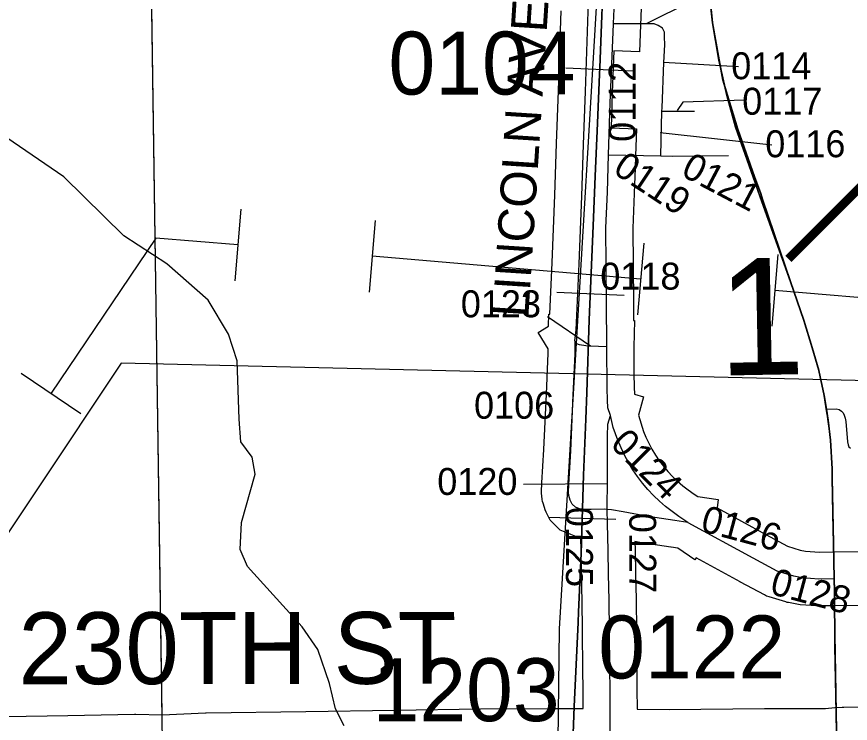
# Model space of a CAD drawing. Extents: x 23.6 to 68.7, y -63 to -29.
# Drawn here: x 43.509 to 44.437, y -46.572 to -45.786 of the extents above; entities that cross this region are included whole.
import ezdxf

# ---------------------------------------------------------------- set-up
doc = ezdxf.new("R2010")
doc.units = 0
for name, color, linetype in [('tdCoHydroRiver', 7, 'Continuous'), ('tdCoInstRd', 7, 'Continuous'), ('tdCoPipe', 7, 'Continuous'), ('tdCoPipe3', 7, 'Continuous'), ('tdCoPriCL', 7, 'Continuous'), ('tdCoPrimary', 7, 'Continuous'), ('tdCoPriNonDiv', 7, 'Continuous'), ('tdCoPriNonDivCL', 7, 'Continuous'), ('tdCoRRCL', 7, 'Continuous'), ('tdCoSecRdNmbr', 7, 'Continuous'), ('tdCoSecRdTxt', 7, 'Continuous'), ('tdCoSecRteBand', 7, 'Continuous'), ('tdCoSecRteCL', 7, 'Continuous'), ('tdCoSectLine', 7, 'Continuous'), ('tdCoSectLinePart', 7, 'Continuous'), ('tdCoSectNmbr', 7, 'Continuous'), ('tdCoSurfConc', 7, 'Continuous'), ('tdCoSurfConcUnbanded', 7, 'Continuous'), ('tdCoSurfGravel', 7, 'Continuous'), ('tdCoSurfGravelUnbanded', 7, 'Continuous'), ('tdStHwyPriRefPost1', 7, 'Continuous')]:
    doc.layers.add(name, color=color, linetype=linetype)

msp = doc.modelspace()

# ---------------------------------------------------------------- linework, layer by layer
at = {"layer": 'tdCoHydroRiver'}
msp.add_lwpolyline([(43.87358, -46.57498), (43.86393, -46.55613), (43.85735, -46.52778), (43.84436, -46.49002), (43.82676, -46.46493), (43.76614, -46.39763), (43.75806, -46.37876), (43.75936, -46.34876), (43.77464, -46.29494), (43.7713, -46.27603), (43.75851, -46.25879), (43.75669, -46.23355), (43.7545, -46.16885), (43.74475, -46.13896), (43.72229, -46.10128), (43.67613, -46.06068), (43.62848, -46.02956), (43.56155, -45.9639), (43.4837, -45.91097)], dxfattribs=at)
at = {"layer": 'tdCoInstRd'}
for p, q in [((44.41089, -46.22273), (44.42158, -46.22228)), ((44.42158, -46.22228), (44.42472, -46.22312)), ((44.42472, -46.22312), (44.42725, -46.22472)), ((44.42725, -46.22472), (44.42912, -46.22654)), ((44.42912, -46.22654), (44.43044, -46.22907)), ((44.43044, -46.22907), (44.43156, -46.23263)), ((44.43156, -46.23263), (44.43212, -46.23647)), ((44.43212, -46.23647), (44.43395, -46.25877)), ((44.43395, -46.25877), (44.4346, -46.26242)), ((44.4346, -46.26242), (44.43559, -46.26467)), ((44.43559, -46.26467), (44.43721, -46.26615))]:
    msp.add_line(p, q, dxfattribs=at)
at = {"layer": 'tdCoPipe'}
msp.add_lwpolyline([(46.10304, -46.17979), (45.58559, -46.28946), (44.97693, -46.20317), (43.62548, -46.17124), (43.25319, -46.72969), (42.68467, -46.77765), (42.3107, -46.83304), (42.01148, -46.92766), (40.92509, -47.18991), (40.11127, -47.31966), (39.6484, -47.46076), (39.18322, -47.45096), (38.62353, -47.68391), (38.15709, -47.72241), (37.61672, -48.03962), (37.05339, -48.16596), (36.16961, -48.17789)], dxfattribs=at)
at = {"layer": 'tdCoPipe3'}
for p, q in [((43.7587, -45.9999), (43.75195, -46.07978)), ((43.90817, -46.01253), (43.90142, -46.09241)), ((44.20711, -46.03778), (44.20036, -46.11767)), ((44.35657, -46.05041), (44.34982, -46.1303)), ((43.51427, -46.18239), (43.58071, -46.22725))]:
    msp.add_line(p, q, dxfattribs=at)
for points in [[(43.75533, -46.03984), (43.66411, -46.03213), (43.54749, -46.20482)], [(44.20373, -46.07773), (43.9048, -46.05247)], [(44.65213, -46.11561), (44.3532, -46.09035)]]:
    msp.add_lwpolyline(points, dxfattribs=at)
at = {"layer": 'tdCoPriCL'}
msp.add_lwpolyline([(44.42187, -46.58466), (44.42091, -46.53437), (44.42001, -46.48685), (44.41952, -46.42396), (44.41922, -46.41143), (44.41828, -46.37218), (44.41761, -46.33904), (44.4168, -46.29893), (44.4168, -46.28882), (44.41508, -46.25701), (44.41236, -46.23482), (44.41046, -46.22238), (44.40817, -46.20744), (44.40225, -46.17958), (44.39486, -46.15418), (44.38548, -46.12384), (44.37069, -46.08069), (44.33668, -45.98664), (44.32885, -45.96453), (44.30946, -45.90874), (44.2996, -45.87336), (44.29075, -45.83424), (44.28361, -45.79274), (44.28123, -45.76909)], dxfattribs=at)
at = {"layer": 'tdCoPrimary'}
for points in [[(44.33098, -45.96391), (44.31237, -45.91151), (44.2956, -45.85657), (44.28399, -45.79274), (44.2747, -45.69881)], [(44.33098, -45.96391), (44.31237, -45.91151), (44.2956, -45.85657), (44.28399, -45.79274), (44.2747, -45.69881)], [(44.42214, -46.57904), (44.42039, -46.48685), (44.41989, -46.42396), (44.4196, -46.41143), (44.41866, -46.37218), (44.41718, -46.29893), (44.41718, -46.28882), (44.41546, -46.25701), (44.41274, -46.23482), (44.41089, -46.22273), (44.40855, -46.20744), (44.40263, -46.17958), (44.39523, -46.15418), (44.38586, -46.12384), (44.37107, -46.08069), (44.34025, -45.99029), (44.33777, -45.98303), (44.33098, -45.96391), (44.31237, -45.91151), (44.2956, -45.85657), (44.28399, -45.79274), (44.2747, -45.69881)], [(44.34025, -45.99029), (44.33777, -45.98303), (44.33098, -45.96391)], [(44.34025, -45.99029), (44.33777, -45.98303), (44.33098, -45.96391)], [(44.42214, -46.57904), (44.42039, -46.48685), (44.41989, -46.42396), (44.4196, -46.41143), (44.41866, -46.37218), (44.41718, -46.29893), (44.41718, -46.28882), (44.41546, -46.25701), (44.41274, -46.23482), (44.41089, -46.22273), (44.40855, -46.20744), (44.40263, -46.17958), (44.39523, -46.15418), (44.38586, -46.12384), (44.37107, -46.08069), (44.34025, -45.99029)], [(44.42214, -46.57904), (44.42039, -46.48685), (44.41989, -46.42396), (44.4196, -46.41143), (44.41866, -46.37218), (44.41718, -46.29893), (44.41718, -46.28882), (44.41546, -46.25701), (44.41274, -46.23482), (44.41089, -46.22273), (44.40855, -46.20744), (44.40263, -46.17958), (44.39523, -46.15418), (44.38586, -46.12384), (44.37107, -46.08069), (44.34025, -45.99029)]]:
    msp.add_lwpolyline(points, dxfattribs=at)
at = {"layer": 'tdCoPriNonDiv'}
msp.add_lwpolyline([(44.28127, -45.76908), (44.28365, -45.79273), (44.29079, -45.83423), (44.29964, -45.87335), (44.3095, -45.90873), (44.32889, -45.96452), (44.33672, -45.98663), (44.37073, -46.08068), (44.38552, -46.12383), (44.40229, -46.17957), (44.40821, -46.20743), (44.41512, -46.257), (44.41684, -46.28881), (44.41684, -46.29892), (44.42227, -46.60348)], dxfattribs=at)
at = {"layer": 'tdCoPriNonDivCL'}
msp.add_lwpolyline([(44.42176, -46.57904), (44.42001, -46.48685), (44.41952, -46.42396), (44.41922, -46.41143), (44.41828, -46.37218), (44.4168, -46.29893), (44.4168, -46.28882), (44.41508, -46.25701), (44.41236, -46.23482), (44.41051, -46.22273), (44.40817, -46.20744), (44.40225, -46.17958), (44.39486, -46.15418), (44.38548, -46.12384), (44.37069, -46.08069), (44.33987, -45.99029), (44.3374, -45.98303), (44.3306, -45.96391), (44.312, -45.91151), (44.29522, -45.85657), (44.28361, -45.79274), (44.27432, -45.69881)], dxfattribs=at)
msp.add_lwpolyline([(44.42176, -46.57904), (44.42001, -46.48685), (44.41952, -46.42396), (44.41922, -46.41143), (44.41828, -46.37218), (44.4168, -46.29893), (44.4168, -46.28882), (44.41508, -46.25701), (44.41236, -46.23482), (44.41051, -46.22273), (44.40817, -46.20744), (44.40225, -46.17958), (44.39486, -46.15418), (44.38548, -46.12384), (44.37069, -46.08069), (44.33987, -45.99029), (44.3374, -45.98303), (44.3306, -45.96391), (44.312, -45.91151), (44.29522, -45.85657), (44.28361, -45.79274), (44.27432, -45.69881)], dxfattribs=at)
at = {"layer": 'tdCoRRCL'}
for p, q in [((44.1955, -45.84633), (44.12058, -45.84299)), ((44.18523, -46.09604), (44.1103, -46.09285)), ((44.17614, -46.34552), (44.10118, -46.34304))]:
    msp.add_line(p, q, dxfattribs=at)
for points in [[(44.1822, -45.22022), (44.17931, -45.29807), (44.17696, -45.35129), (44.17538, -45.40241), (44.17093, -45.49311), (44.16857, -45.55654), (44.16621, -45.63335), (44.16463, -45.67844), (44.1607, -45.78487), (44.15814, -45.84247), (44.15782, -45.84962), (44.15572, -45.90414), (44.1531, -45.96312), (44.151, -46.01844), (44.14655, -46.12303), (44.14366, -46.20403), (44.14256, -46.23388), (44.14026, -46.29604), (44.13737, -46.38307), (44.13471, -46.44821), (44.13423, -46.46014), (44.12977, -46.55347), (44.12741, -46.61323)], [(44.12741, -46.61323), (44.12977, -46.55347), (44.13423, -46.46014), (44.13471, -46.44821), (44.13737, -46.38307), (44.14026, -46.29604), (44.14256, -46.23388), (44.14366, -46.20403), (44.14655, -46.12303), (44.151, -46.01844), (44.1531, -45.96312), (44.15572, -45.90414), (44.15782, -45.84962), (44.15814, -45.84247), (44.1607, -45.78487), (44.16463, -45.67844), (44.16621, -45.63335), (44.16857, -45.55654), (44.17093, -45.49311), (44.17538, -45.40241), (44.17696, -45.35129), (44.17931, -45.29807), (44.1822, -45.22022)], [(42.74649, -50.31687), (42.74164, -50.05586), (42.75629, -49.92628), (42.79153, -49.80443), (42.85538, -49.70442), (42.92256, -49.6249), (42.97285, -49.5992), (43.92922, -48.85362), (44.03877, -48.74532), (44.06896, -48.71007), (44.09338, -48.67223), (44.10531, -48.65074), (44.10984, -48.63845), (44.1114, -48.63233), (44.11198, -48.62671), (44.11322, -48.05326), (44.10862, -47.52765), (44.11109, -47.4487), (44.10535, -47.15357), (44.11332, -46.467), (44.17329, -45.46369)]]:
    msp.add_lwpolyline(points, dxfattribs=at)
at = {"layer": 'tdCoSecRdNmbr'}
for p, q in [((44.26005, -45.7688), (44.20973, -45.7937)), ((44.31265, -45.84143), (44.2292, -45.83693)), ((44.34994, -45.92874), (44.22565, -45.915)), ((44.1, -46.11926), (44.14798, -46.15223))]:
    msp.add_line(p, q, dxfattribs=at)
for points in [[(44.31926, -45.87878), (44.25081, -45.88097), (44.24451, -45.8901)], [(44.07318, -46.30616), (44.16637, -46.30522), (44.16637, -46.30522)]]:
    msp.add_lwpolyline(points, dxfattribs=at)
at = {"layer": 'tdCoSecRteBand'}
for points in [[(44.20484, -45.7646), (44.2039, -45.78614), (44.20355, -45.7949), (44.20234, -45.82487), (44.17387, -45.82373), (44.17219, -45.87021), (44.17088, -45.90952), (44.199, -45.91049), (44.19797, -45.94047), (44.1975, -45.95419), (44.19668, -45.98206), (44.19667, -45.98225), (44.19667, -45.98243), (44.19505, -46.02114), (44.19571, -46.10359), (44.19571, -46.1036), (44.19571, -46.10362), (44.19584, -46.12306), (44.19585, -46.12404), (44.19684, -46.12407), (44.19605, -46.15356), (44.19625, -46.18305), (44.19636, -46.19818), (44.19674, -46.20599), (44.20697, -46.20882), (44.20132, -46.22923), (44.20698, -46.24738), (44.2095, -46.2536), (44.21272, -46.2605), (44.21631, -46.26723), (44.22025, -46.27375), (44.22453, -46.28006), (44.22914, -46.28614), (44.23405, -46.29196), (44.23927, -46.29752), (44.24478, -46.30279), (44.25055, -46.30776), (44.25658, -46.31243), (44.26342, -46.31716), (44.26732, -46.31982), (44.29005, -46.32295), (44.28877, -46.33229), (44.34321, -46.36218), (44.36717, -46.37489), (44.38152, -46.37934), (44.38734, -46.38048), (44.40288, -46.38158), (44.41932, -46.38143), (44.44932, -46.38115)], [(43.45001, -46.5654), (43.56587, -46.56343), (43.64014, -46.56195), (43.64087, -46.56194), (43.64159, -46.56196), (43.67112, -46.5628), (43.71914, -46.56066), (43.71958, -46.56064), (43.72003, -46.56063), (43.83084, -46.55899), (43.83086, -46.55899), (43.83089, -46.55899), (43.93013, -46.55767), (44.02542, -46.55603), (44.02562, -46.55603), (44.02581, -46.55603), (44.10357, -46.5557), (44.10364, -46.5557), (44.1037, -46.5557), (44.13974, -46.5557), (44.13968, -46.53468), (44.13942, -46.51262), (44.13942, -46.51258), (44.13942, -46.51254), (44.13904, -46.46906), (44.13904, -46.46905), (44.13904, -46.46903), (44.13879, -46.43577), (44.13803, -46.40686), (44.13803, -46.40675), (44.13803, -46.40665), (44.13752, -46.38048), (44.13711, -46.36477), (44.13702, -46.36477), (44.13701, -46.36429), (44.13148, -46.36429), (44.12602, -46.36206), (44.11972, -46.35948), (44.11413, -46.3572), (44.10987, -46.35293), (44.10643, -46.34949), (44.10299, -46.34605), (44.10081, -46.3417), (44.09852, -46.33712), (44.09733, -46.33473), (44.09657, -46.33217), (44.09514, -46.3273), (44.09453, -46.32522), (44.09422, -46.32307), (44.09365, -46.31907), (44.09328, -46.31646), (44.09336, -46.31382), (44.09365, -46.30523), (44.09367, -46.30481), (44.09369, -46.30439), (44.09597, -46.26739), (44.09882, -46.20582), (44.1008, -46.16018), (44.10087, -46.15551), (44.08973, -46.1374), (44.10126, -46.13031), (44.10147, -46.11677), (44.10264, -46.11679), (44.10533, -46.05949), (44.10828, -45.98446), (44.11025, -45.92709), (44.11223, -45.86817), (44.11223, -45.86813), (44.11223, -45.86809), (44.11543, -45.77917)], [(44.44987, -46.44115), (44.41988, -46.44143), (44.40223, -46.44159), (44.40103, -46.4416), (44.39984, -46.44152), (44.38126, -46.4402), (44.37941, -46.44007), (44.3776, -46.43971), (44.36839, -46.43791), (44.36682, -46.4376), (44.36529, -46.43713), (44.34672, -46.43137), (44.34402, -46.43054), (44.34153, -46.42921), (44.31489, -46.41507), (44.31471, -46.41497), (44.31452, -46.41487), (44.26563, -46.38803), (44.26411, -46.39027), (44.24516, -46.37734), (44.2378, -46.37633), (44.23756, -46.37629), (44.23733, -46.37626), (44.20755, -46.37168), (44.20709, -46.37161), (44.20664, -46.37152), (44.19726, -46.36978), (44.1975, -46.37904), (44.1975, -46.37913), (44.1975, -46.37922), (44.19801, -46.40539), (44.19877, -46.43448), (44.19878, -46.43476), (44.19878, -46.43504), (44.19904, -46.46855), (44.19942, -46.51197), (44.19967, -46.53412), (44.19968, -46.53424), (44.19968, -46.53437), (44.19974, -46.55648), (44.23534, -46.55668)], [(44.23534, -46.55668), (44.34148, -46.5557), (44.34158, -46.5557), (44.34169, -46.5557), (44.40948, -46.55554), (44.41999, -46.55474), (44.42795, -46.55414), (44.42889, -46.55407), (44.42984, -46.55406), (44.51023, -46.55307)]]:
    msp.add_lwpolyline(points, dxfattribs=at)
at = {"layer": 'tdCoSecRteCL'}
for p, q in [((44.22615, -45.94061), (44.22748, -45.89098)), ((44.22748, -45.89098), (44.26387, -45.8908)), ((44.16799, -45.93944), (44.22615, -45.94061))]:
    msp.add_line(p, q, dxfattribs=at)
for points in [[(44.13101, -46.14723), (44.13062, -46.1466), (44.13185, -46.13427), (44.1353, -46.06078), (44.13826, -45.98557), (44.14024, -45.92811), (44.14221, -45.86917), (44.14542, -45.78015), (44.14764, -45.70394), (44.14961, -45.66029), (44.15151, -45.61422)], [(44.17357, -45.79369), (44.17393, -45.78488), (44.17491, -45.76219), (44.17656, -45.74822), (44.1855, -45.71099), (44.18643, -45.70712), (44.19728, -45.66224), (44.19941, -45.65703), (44.20187, -45.65196), (44.20464, -45.64706), (44.20772, -45.64234), (44.21109, -45.63783), (44.21806, -45.63328), (44.22721, -45.62793), (44.23999, -45.62206), (44.25018, -45.61791), (44.26175, -45.61564), (44.27327, -45.61397), (44.30357, -45.61119), (44.32256, -45.6107), (44.44618, -45.60946), (44.4833, -45.6089), (44.64231, -45.6065), (44.65935, -45.60635)], [(44.16799, -45.93944), (44.16998, -45.88155), (44.17212, -45.82976), (44.17357, -45.79369)], [(44.22748, -45.89098), (44.22757, -45.88733), (44.22958, -45.83693), (44.23072, -45.81718), (44.23044, -45.8083), (44.23015, -45.80286), (44.2282, -45.79869), (44.22815, -45.79856), (44.22328, -45.79541), (44.21898, -45.7937), (44.21011, -45.7937), (44.1892, -45.7937), (44.17357, -45.79369)], [(44.16605, -46.15326), (44.16571, -46.10383), (44.16505, -46.02064), (44.16669, -45.98118), (44.16751, -45.95323), (44.16799, -45.93944)], [(44.22615, -45.94061), (44.23903, -45.94087), (44.30173, -45.9403)], [(44.16645, -46.33421), (44.16366, -46.33399), (44.14855, -46.33429), (44.13738, -46.33429), (44.13108, -46.33172), (44.12764, -46.32828), (44.12535, -46.3237), (44.12392, -46.31883), (44.12335, -46.31482), (44.12363, -46.30623), (44.12592, -46.26901), (44.12879, -46.20716), (44.13079, -46.16106), (44.13101, -46.14723)], [(44.16605, -46.15326), (44.15676, -46.15301), (44.14542, -46.15252), (44.13802, -46.15129), (44.13555, -46.1508), (44.13259, -46.14981), (44.13101, -46.14723)], [(44.17006, -46.22974), (44.16735, -46.22105), (44.16702, -46.2125), (44.16636, -46.19902), (44.16605, -46.15326)], [(44.16645, -46.33421), (44.16636, -46.3297), (44.16674, -46.30522), (44.16674, -46.27539), (44.167, -46.25269), (44.16738, -46.23943), (44.17006, -46.22974)], [(44.25624, -46.34858), (44.24643, -46.34188), (44.23886, -46.33664), (44.23158, -46.33101), (44.2246, -46.325), (44.21795, -46.31863), (44.21165, -46.31192), (44.20571, -46.30489), (44.20014, -46.29755), (44.19498, -46.28993), (44.19022, -46.28205), (44.18588, -46.27393), (44.18198, -46.26559), (44.17853, -46.25705), (44.17327, -46.24308), (44.17006, -46.22974)], [(44.16999, -46.58615), (44.1698, -46.57896), (44.16968, -46.53446), (44.16942, -46.51228), (44.16904, -46.4688), (44.16878, -46.43527), (44.16802, -46.40607), (44.16751, -46.37981), (44.16674, -46.34997), (44.16645, -46.33421)], [(44.25624, -46.34858), (44.24189, -46.34661), (44.21211, -46.34202), (44.18434, -46.33687), (44.17117, -46.33458), (44.16645, -46.33421)], [(44.4196, -46.41143), (44.40196, -46.41159), (44.38338, -46.41028), (44.37417, -46.40847), (44.35559, -46.40271), (44.32896, -46.38858), (44.25679, -46.34895), (44.25624, -46.34858)]]:
    msp.add_lwpolyline(points, dxfattribs=at)
at = {"layer": 'tdCoSectLine'}
msp.add_lwpolyline([(43.65695, -45.62191), (43.67102, -46.59281)], dxfattribs=at)
at = {"layer": 'tdCoSectLinePart'}
msp.add_lwpolyline([(43.65738, -45.65187), (43.67059, -46.56279)], dxfattribs=at)
at = {"layer": 'tdCoSurfConc'}
for points in [[(44.17357, -45.79369), (44.17393, -45.78488), (44.17491, -45.76219), (44.17656, -45.74822), (44.1855, -45.71099), (44.18643, -45.70712), (44.19728, -45.66224), (44.19941, -45.65703), (44.20187, -45.65196), (44.20464, -45.64706), (44.20772, -45.64234), (44.21109, -45.63783), (44.21806, -45.63328), (44.22721, -45.62793), (44.23999, -45.62206), (44.25018, -45.61791), (44.26175, -45.61564), (44.27327, -45.61397), (44.30357, -45.61119), (44.32256, -45.6107), (44.44618, -45.60946)], [(44.4196, -46.41143), (44.40196, -46.41159), (44.38338, -46.41028), (44.37417, -46.40847), (44.35559, -46.40271), (44.32896, -46.38858), (44.25679, -46.34895), (44.25624, -46.34858), (44.24643, -46.34188), (44.23886, -46.33664), (44.23158, -46.33101), (44.2246, -46.325), (44.21795, -46.31863), (44.21165, -46.31192), (44.20571, -46.30489), (44.20014, -46.29755), (44.19498, -46.28993), (44.19022, -46.28205), (44.18588, -46.27393), (44.18198, -46.26559), (44.17853, -46.25705), (44.17327, -46.24308), (44.17006, -46.22974), (44.16735, -46.22105), (44.16702, -46.2125), (44.16636, -46.19902), (44.16605, -46.15326), (44.16571, -46.10383), (44.16505, -46.02064), (44.16669, -45.98118), (44.16751, -45.95323), (44.16799, -45.93944)]]:
    msp.add_lwpolyline(points, dxfattribs=at)
at = {"layer": 'tdCoSurfConcUnbanded'}
msp.add_lwpolyline([(44.16799, -45.93944), (44.16998, -45.88155), (44.17212, -45.82976), (44.17357, -45.79369)], dxfattribs=at)
at = {"layer": 'tdCoSurfGravel'}
for points in [[(44.12764, -46.32828), (44.12535, -46.3237), (44.12392, -46.31883), (44.12335, -46.31482), (44.12363, -46.30623), (44.12592, -46.26901), (44.12879, -46.20716), (44.13079, -46.16106), (44.13101, -46.14723), (44.13062, -46.1466), (44.13185, -46.13427), (44.1353, -46.06078), (44.13826, -45.98557), (44.14024, -45.92811), (44.14221, -45.86917), (44.14542, -45.78015), (44.14764, -45.70394), (44.14961, -45.66029), (44.15151, -45.61422)], [(44.16605, -46.15326), (44.15676, -46.15301), (44.14542, -46.15252), (44.13802, -46.15129), (44.13555, -46.1508), (44.13259, -46.14981), (44.13101, -46.14723)], [(44.25624, -46.34858), (44.24189, -46.34661), (44.21211, -46.34202), (44.18434, -46.33687), (44.17117, -46.33458), (44.16645, -46.33421), (44.16636, -46.3297), (44.16674, -46.30522), (44.16674, -46.27539), (44.167, -46.25269), (44.16738, -46.23943), (44.17006, -46.22974)], [(44.16645, -46.33421), (44.16366, -46.33399), (44.14855, -46.33429), (44.13738, -46.33429), (44.13108, -46.33172), (44.12764, -46.32828)], [(44.17253, -46.71469), (44.17248, -46.70964), (44.17197, -46.68197), (44.17095, -46.6246), (44.16999, -46.58615), (44.1698, -46.57896), (44.16968, -46.53446), (44.16942, -46.51228), (44.16904, -46.4688), (44.16878, -46.43527), (44.16802, -46.40607), (44.16751, -46.37981), (44.16674, -46.34997), (44.16645, -46.33421)]]:
    msp.add_lwpolyline(points, dxfattribs=at)
at = {"layer": 'tdCoSurfGravelUnbanded'}
for p, q in [((44.22615, -45.94061), (44.22748, -45.89098)), ((44.22748, -45.89098), (44.26387, -45.8908)), ((44.16799, -45.93944), (44.22615, -45.94061))]:
    msp.add_line(p, q, dxfattribs=at)
for points in [[(44.22748, -45.89098), (44.22757, -45.88733), (44.22958, -45.83693), (44.23072, -45.81718), (44.23044, -45.8083), (44.23015, -45.80286), (44.2282, -45.79869), (44.22815, -45.79856), (44.22328, -45.79541), (44.21898, -45.7937), (44.21011, -45.7937), (44.1892, -45.7937), (44.17357, -45.79369)], [(44.22615, -45.94061), (44.23903, -45.94087), (44.30173, -45.9403)]]:
    msp.add_lwpolyline(points, dxfattribs=at)

# ---------------------------------------------------------------- texts
at = {"layer": 'tdCoSecRdNmbr'}
for s, height, rotation, p in [('0104', 0.07, 0.03428, (43.92302, -45.87247)), ('0114', 0.03, 0.03451, (44.30458, -45.85541)), ('0112', 0.03, 90.03228, (44.19818, -45.92512)), ('0117', 0.03, 0.03453, (44.3168, -45.89484)), ('0116', 0.03, 0.03454, (44.34247, -45.94226)), ('0119', 0.03, 326.41315, (44.17156, -45.95894)), ('0121', 0.03, 332.2562, (44.24732, -45.96202)), ('0118', 0.03, 0.03441, (44.15885, -46.08954)), ('0123', 0.03, 0.03443, (44.00356, -46.12035)), ('0106', 0.03, 0.03429, (44.01827, -46.23321)), ('0124', 0.03, 315.03366, (44.16868, -46.26269)), ('0120', 0.03, 0.03427, (43.97734, -46.31806)), ('0125', 0.03, 270.03224, (44.12055, -46.33131)), ('0126', 0.03, 345.0345, (44.26919, -46.35807)), ('0127', 0.03, 270.03229, (44.19101, -46.33792)), ('0128', 0.03, 345.0345, (44.34649, -46.42787)), ('0122', 0.07, 0.03444, (44.1566, -46.52226)), ('1203', 0.07, 0.03447, (43.90531, -46.5699))]:
    msp.add_text(s, height=height, rotation=rotation, dxfattribs=at).set_placement(p)
at = {"layer": 'tdCoSecRdTxt'}
for s, height, rotation, p in [('LINCOLN AVE', 0.04, 86.32708, (44.07863, -46.12121)), ('230TH ST', 0.08, 0.05745, (43.51116, -46.5287))]:
    msp.add_text(s, height=height, rotation=rotation, dxfattribs=at).set_placement(p)
at = {"layer": 'tdCoSectNmbr'}
msp.add_text('1', height=0.13, rotation=1.03446, dxfattribs=at).set_placement((44.29068, -46.18525))
at = {"layer": 'tdStHwyPriRefPost1'}
msp.add_text('‒‒66', height=0.1, rotation=45, dxfattribs=at).set_placement((44.39424, -46.08142))

doc.saveas('drawing.dxf')
